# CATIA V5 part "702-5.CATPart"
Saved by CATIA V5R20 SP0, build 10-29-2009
Part number: 702-5
Source: Unknown
Property "ARTICLENO": "702-5"
Property "BOMINFO": "702-5"
Property "CODE": "702-5"
Property "L": "150.000"
Property "LINA": "702-5"
Property "NB": "702-5"
Property "NBSYN": "$CODE."
Property "NN": "702"
Property "SUPPLIER": "CF"
Bounding box of the stored display mesh (mm): x -107 to 0, y 0 to 150, z -15 to 15
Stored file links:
  C:\Users\Utente\Desktop\3D files 702\702-5.CATPart
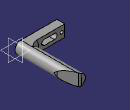
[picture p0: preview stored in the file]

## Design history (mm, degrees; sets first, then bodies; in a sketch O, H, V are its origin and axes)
Body1 "Geometry.1" (main body)
  Solid1 "702-5.catpart": solid without history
